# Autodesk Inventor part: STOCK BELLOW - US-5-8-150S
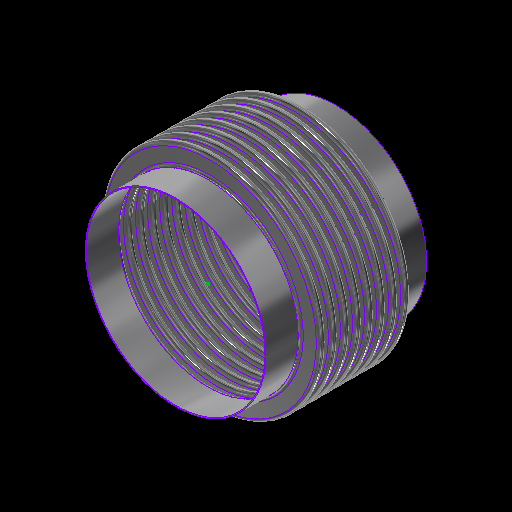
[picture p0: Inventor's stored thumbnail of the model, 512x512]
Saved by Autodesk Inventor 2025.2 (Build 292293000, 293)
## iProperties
Category: 22 GA (0.030 THICK)
RuleStatus: InUse
Created: 2024-01
Part Number: STOCK BELLOW - US-5-8-150S
Project: =STOCK BELLOWS: <Stock Number><SFILL>
Material: ASTM A240-304
Description: =STOCK BELLOWS: <Stock Number>, <SID_> I.D., <SOD_> O.D., <SPLY_> PLY, <Category>, <SNET_CONS> CONS.<PITCH_><STANGENT_> TANGENT<SFILL>
Document SubType Name: Sheet Metal
Designer: GS
Stock Number: U.S-5-8-150S
Surface Area: 3291.39 cm^2
Volume: 124.624 cm^3
Sheet Metal Rule: Default
Appearance: STAINLESS STEEL
Mass: 1004.13 g
Density: 8.05729 g/cm^3
THK: 0.036
ID: 3.500
OD: 4.250
CONS_: 2
PITCH: 0.500
TANGENT: 0.500
BELLOWS_UPSET: 0.000
d79: 1.000
d82: 1.000
d83: 26.000
d84: 24.000
d174: 8
d214: 8
STHK_: 0.030
SID_: 5.563
SOD_: 6.813
SPITCH_: 0.375
STANGENT__: 1.000
SBELLOWS_UPSET_: 0.000
SDIFF_TAN: 1.000
d252: 2
d275: 2
d287: 0.050
d289: 0.500
d290: 0.000
SOD_NECK: 5 5/8
PLY: 1
PSET: 4.178
PBAR: 1.035
COUNTER: 1.500
NET_TUBE: 3.071
CONS: 2
S_CONS: 0
NET_CONS: 2
ID_M: 88.90 mm
OD_M: 107.95 mm
THK_M: 0.91 mm
ID_U: 3.500 in
OD_U: 4.250 in
THK_U: 0.036 in
TANGENT2: 0.500
TAN_TO_TAN: 1.000 in
d80: 2.571
d81: 10
SID: 2.375
SCONS_: 8
SPITCH: 0.250
STANGENT_: 1.000
SBELLOWS_UPSET: 0.000
SNET_CONS: 8
SS_CONS: 0
SCONS: 8
d190: 8
d191: 1
d192: 1
d193: 8
d194: 0
SIZE: 5.00
PRESSURE: 150
d230: 8
STANGENT: 4.000
SPLY_: 1
d233: 8
d234: 0
d263: 2
d265: 1
d268: 2
d269: 0
d286: 2
d288: 1
d291: 2
d292: 0
SREROLL: 0.750
BLETP: 0.000 ul
PRES_Copy: 85
MATTABLE: 20 GA (0.036 THICK)
PART_NUMBER: U.S-5-8-150S
PITCH_: =, <SPITCH_> PITCH,
CFILL: .
SFILL: .
MESH: ,
COMP: 0.69
EXT: 0.35
LAT: 0.11
ANG: 573
ASR: 1531
LSR: 8791
ANSR: 115
PRES: 150
COMPM: 6.9
EXTM: 3.45
LATM: 1.10
ASRM: 268.124
PRESM: 10.342
LSRM: 1539.568
ANSRM: 20.14
TEMPMIN: 20
TEMPMAX: 800
TEMPMINM: -7
TEMPMAXM: 427
WEIGHTM: 1.004
WEIGHT: 2.214
Author: GS
Keywords: 20 GA (0.036 THICK)
Comments: =STOCK BELLOW - <STOCK NUMBER>
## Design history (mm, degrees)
sketch "Sketch2"
  geometry: L1 (0, -177.245)-(0, 562.856) reference; L2 (45.364, 0)-(44.45, 0); L3 (48.082, -2.718)-(50.343, -2.718); L4 (48.082, -3.632)-(50.343, -3.632); L5 (50.343, -9.982)-(48.082, -9.982); L6 (50.343, -9.068)-(48.082, -9.068); L7 (45.364, -12.7)-(44.45, -12.7); L8 (48.082, 0)-(48.082, -12.7); L9 (50.343, -6.35)-(53.975, -6.35); L10 (44.45, 0)-(44.45, -12.7); L11 (20.376, 102.841)-(20.376, 101.926); L12 (58.262, 457.127)-(58.262, 349.177); L13 (58.262, 444.427)-(58.262, 336.477); L14 (93.133, -58.817)-(93.133, -71.517); L15 (118.746, -66.401)-(118.746, -66.401); L16 (50.343, -9.068)-(50.343, -9.982); L17 (48.082, -9.068)-(48.082, -9.982); L18 (48.082, -9.525)-(50.343, -9.525); L19 (53.975, 0)-(53.975, -12.7); L20 (-50.343, -9.068)-(-50.343, -9.982); L21 (-50.343, -2.718)-(-48.082, -2.718); L22 (-50.343, -3.632)-(-48.082, -3.632); L23 (-48.082, -9.068)-(-50.343, -9.068); L24 (-50.343, -9.525)-(-48.082, -9.525); L25 (-48.082, -9.982)-(-50.343, -9.982); L26 (-48.082, -9.068)-(-48.082, -9.982); L27 (-44.45, 0.653)-(-44.45, -12.047); L28 (-48.082, -6.35)-(-44.45, -6.35); L29 (-50.343, 0.653)-(-50.343, -12.7); L30 (-53.061, 0)-(-53.975, 0); L31 (-53.975, 0)-(-53.975, -12.7); L32 (-53.061, -12.7)-(-53.975, -12.7); A1 r 2.718 centre (48.082, 0) between (45.364, 0) and (48.082, -2.718); A2 r 3.632 centre (48.082, 0) between (44.45, 0) and (48.082, -3.632); A3 r 3.632 centre (50.343, -6.35) between (50.343, -9.982) and (50.343, -2.718); A4 r 2.718 centre (50.343, -6.35) between (50.343, -9.068) and (50.343, -3.632); A5 r 2.718 centre (48.082, -12.7) between (48.082, -9.982) and (45.364, -12.7); A6 r 3.632 centre (48.082, -12.7) between (48.082, -9.068) and (44.45, -12.7); A7 r 3.175 centre (50.343, -6.35) between (50.343, -9.525) and (53.518, -6.35); A8 r 3.175 centre (48.082, -12.7) between (48.082, -9.525) and (44.907, -12.7); A9 r 2.718 centre (-50.343, -12.7) between (-50.343, -9.982) and (-53.061, -12.7); A10 r 2.718 centre (-48.082, -6.35) between (-48.082, -9.068) and (-48.082, -3.632); A11 r 3.175 centre (-48.082, -6.35) between (-48.082, -9.525) and (-44.907, -6.35); A12 r 3.632 centre (-48.082, -6.35) between (-48.082, -9.982) and (-48.082, -2.718); A13 r 3.175 centre (-50.343, -12.7) between (-50.343, -9.525) and (-53.518, -12.7); A14 r 3.632 centre (-50.343, -12.7) between (-50.343, -9.068) and (-53.975, -12.7); A15 r 2.718 centre (-50.343, 0) between (-53.061, 0) and (-50.343, -2.718); A16 r 3.632 centre (-50.343, 0) between (-53.975, 0) and (-50.343, -3.632); 10 further points
  constraints: 62 end point, 38 point on circle, 20 tangent, 16 centre point, 12 parallel, 9 midpoint, 7 vertical, 6 coincident, 6 concentric, 6 point on line, 4 equal radius, 4 perpendicular, 3 horizontal, 1 collinear, 1 horizontal alignment, 10 other
  dimensions: "THK" = 0.9144 distance of L11.start L11.end; "ID" = 88.9 distance of L11.end point (20.376, 13.026); "OD" = 107.95 distance of L12.start L12.end; "PITCH" = 12.7 distance of L12.start L13.start; "TANGENT" = 12.7 distance of L14.start L14.end; "BELLOWS_UPSET" = 0 distance of L15.start L15.end; "d43" = 88.9 diameter of L10 L1 (= ID); "d44" = 107.95 diameter of L9.end L1 (= OD); "d45" = 0.9144 distance between parallel lines of L5 L6 (computed from THK, PLY); "d46" = 3.6322 radius of A3 (computed from PITCH, THK, PLY); "UPSET_PITCH" = 12.7 distance of L2.end L7.end (derived); "SIDEWALL_ANGLE" = 360 deg dimension on L3 L9 (derived); "CON_GAP" = 5.4356 distance of point (48.082, -9.068) point (48.082, -3.632) (derived); "TAN1" = 4.98728 dimension on A8 (derived); "TAN2" = 4.98728 dimension on A7 (derived); "LEG1" = 2.2606 distance of L18.start L18.end (derived); "d278" = 0.9144 distance between parallel lines of L25 L23 (derived); "d279" = 3.6322 radius of A12 (derived); "d280" = 12.7 distance of L30.end L31.end (derived); "d281" = 360 deg dimension on L21 L28 (derived); "d282" = 5.4356 distance of point (-50.343, -9.068) point (-50.343, -3.632) (derived); "d283" = 4.98728 dimension on A13 (derived); "d284" = 4.98728 dimension on A11 (derived); "d285" = 2.2606 distance of L24.start L24.end (derived); "d293" = 88.9 diameter of L27 L1 (derived); "d294" = 107.95 diameter of L31 L1 (derived)
  node "Sketch Rectangular Pattern1" dims "d31" = 25.4, "ID" = 88.9
  node "Sketch Rectangular Pattern2" dims "d39" = 25.4, "PITCH" = 12.7
revolve "CONS" stored, may be unused: angle "d48" = 90 deg
node "BELLOW MIDPLANE"
pattern_linear "Rectangular Pattern2" dims "d52" = 12.7 (= UPSET_PITCH)
sketch "Sketch5"
  geometry: C1 r 45.364 at (0, 0) reference; C2 r 44.45 at (0, 0) reference
extrude "TANGENT" new body sketch "Sketch5" distance "d53" = 12.7 (= TANGENT); taper "d54" = 0 deg
revolve "SAMETAN" stored, may be unused: angle "d65" = 90 deg
revolve "DIFFTAN" stored, may be unused: angle "d70" = 90 deg
sketch "Sketch9"
  geometry: L1 (53.319, 0)-(-53.319, 0) reference; L2 (0, -17.78)-(0, 17.78) reference; L3 (38.085, 0)-(-38.085, 0); L4 (38.085, -11.906)-(38.085, 11.906); L5 (25.385, -11.906)-(25.385, 11.906); L6 (13.15, 11.906)-(13.15, -11.906); L7 (-25.385, -11.906)-(-25.385, 11.906); L8 (-38.085, -11.906)-(-38.085, 11.906); L9 (37.291, -11.906)-(37.291, 11.906); L10 (38.085, -11.906)-(37.291, -11.906); L11 (38.085, 11.906)-(37.291, 11.906); L12 (13.546, 11.906)-(12.753, 11.906); L13 (12.753, 11.906)-(12.753, -11.906); L14 (12.753, -11.906)-(13.546, -11.906); L15 (13.546, -11.906)-(13.546, 11.906); L16 (-13.546, 11.906)-(-13.546, -11.906); L17 (-13.15, 11.906)-(-13.15, -11.906); L18 (-13.546, -11.906)-(-12.753, -11.906); L19 (-12.753, -11.906)-(-12.753, 11.906); L20 (-12.753, 11.906)-(-13.546, 11.906); L21 (-38.085, -11.906)-(-37.291, -11.906); L22 (-37.291, -11.906)-(-37.291, 11.906); L23 (-37.291, 11.906)-(-38.085, 11.906); L24 (-38.085, 11.906)-(-38.085, -11.906); L25 (38.085, -0.397)-(-38.085, -0.397); L26 (-38.085, -0.397)-(-38.085, 0.397); L27 (-38.085, 0.397)-(38.085, 0.397); L28 (38.085, 0.397)-(38.085, -0.397); L29 (-38.085, 11.906)-(38.085, 11.906); L30 (38.085, 11.906)-(38.085, 12.7); L31 (38.085, 12.7)-(-38.085, 12.7); L32 (-38.085, 12.7)-(-38.085, 11.906); L33 (38.085, -11.906)-(-38.085, -11.906); L34 (-38.085, -11.906)-(-38.085, -12.7); L35 (-38.085, -12.7)-(38.085, -12.7); L36 (38.085, -12.7)-(38.085, -11.906); 30 further points
  constraints: 68 end point, 13 midpoint, 13 parallel, 8 horizontal, 7 perpendicular, 6 equal length, 3 point on line, 2 vertical, 14 other
  dimensions: "d115" = 23.8125 distance of L4.start L4.end (derived); "d116" = 12.7 distance between parallel lines of L4 L5 (derived); "d117" = 12.23516 distance between parallel lines of L5 L6 (derived); "d125" = 38.53427 distance between parallel lines of L7 L6 (derived); "d127" = 12.7 distance between parallel lines of L8 L7 (derived); "d128" = 24.93516 distance between parallel lines of L6 L4 (derived); "d130" = 76.16943 distance between parallel lines of L8 L4 (derived); "RULER_THK" = 0.79375 distance between parallel lines of L4 L9; "d135" = 0.79375 distance of L13.end L14.end (derived); "d138" = 26.29911 distance of L13.end L16.end (derived); "d143" = 0.79375 distance of L22.end L8.end (derived); "d144" = 0.79375 distance between parallel lines of L27 L25 (derived)
extrude "RULER" join sketch "Sketch9" distance "d149" = 0.79375 (derived); taper "d150" = 0 deg
extrude "BARS" join sketch "Sketch9" distance "d151" = 0.79375 (derived); taper "d152" = 0 deg
pattern_linear "Rectangular Pattern4" dims "d155" = 26.29911 (derived)
sketch "Sketch13"
  geometry: L1 (93.149, -52.467)-(93.149, -77.867); L2 (71.412, 0)-(70.65, 0); L3 (71.412, -9.525)-(70.65, -9.525); L4 (83.763, -7.525)-(73.412, -7.525); L5 (83.763, -6.763)-(73.412, -6.763); L6 (83.763, -4.763)-(86.525, -4.763); L7 (73.412, -2)-(83.763, -2); L8 (73.412, 0)-(73.412, -9.525); L9 (70.65, 0)-(70.65, -9.525); L10 (58.254, -323.381)-(58.254, -496.431); L11 (58.254, -332.906)-(58.254, -505.956); L12 (58.254, -351.956)-(58.254, -525.006); L13 (58.254, -361.481)-(58.254, -534.531); L14 (58.254, -371.006)-(58.254, -544.056); L15 (58.254, -380.531)-(58.254, -553.581); L16 (58.254, -390.056)-(58.254, -563.106); L17 (58.254, -342.431)-(58.254, -515.481); L18 (20.376, 102.688)-(20.376, 101.926); L19 (73.412, -2.762)-(83.763, -2.762); L20 (0, -696.265)-(0, 235.847) reference; L21 (-23.752, 0)-(142.514, 0) reference; A1 r 2 centre (73.412, 0) between (71.412, 0) and (73.412, -2); A2 r 2 centre (73.412, -9.525) between (73.412, -7.525) and (71.412, -9.525); A3 r 2.762 centre (73.412, -9.525) between (73.412, -6.763) and (70.65, -9.525); A4 r 2 centre (83.763, -4.763) between (83.763, -6.763) and (83.763, -2.762); A5 r 2.762 centre (83.763, -4.763) between (83.763, -7.525) and (83.763, -2); A6 r 2.762 centre (73.412, 0) between (70.65, 0) and (73.412, -2.762); 6 further points; 1 other entity
  constraints: 38 end point, 15 point on circle, 9 tangent, 6 centre point, 6 parallel, 5 vertical alignment, 4 point on line, 4 vertical, 3 coincident, 3 concentric, 2 collinear, 2 equal radius, 1 horizontal, 1 perpendicular, 23 other
  dimensions: "SBELLOWS_UPSET_" = 0 distance of point (118.762, -66.401) point (118.762, -66.401); "STOTAL_THK_BELLOW__" = 0.762 distance between parallel lines of L4 L5 (derived); "d224" = 2.76225 radius of A5 (derived); "d225" = 9.525 distance of L2.end L3.end (derived); "SSIDEWALL_ANGLE_" = 360 deg dimension on L7 L6 (derived); "SSCON_GAP_" = 4.0005 distance of point (73.412, -6.763) point (73.412, -2.762) (derived); "d235" = 141.3002 diameter of L9 L20 (derived); "d236" = 173.0502 diameter of L6.end L20 (derived)
  node "Sketch Rectangular Pattern4" dims "d228" = 25.4
  node "Sketch Rectangular Pattern5" dims "d229" = 25.4
revolve "SBELLOW" stored, may be unused: angle "d197" = 90 deg
pattern_linear "Rectangular Pattern5" dims "d204" = 9.525 (derived)
revolve "STANGENT" stored, may be unused: angle "d240" = 90 deg
revolve "SSAMETAN" stored, may be unused: angle "d241" = 90 deg
revolve "SDIFFTAN" stored, may be unused: angle "d246" = 90 deg
revolve "INVCON" stored, may be unused: angle "d295" = 90 deg
pattern_linear "Rectangular Pattern6" dims "d298" = 12.7 (derived)
revolve "INVTANGENT" stored, may be unused: angle "d302" = 90 deg
revolve "INVSAMETAN" stored, may be unused: angle "d307" = 90 deg
revolve "INVDIFFTAN" stored, may be unused: angle "d312" = 90 deg
sketch "ID BELLOW MOUNT CALC"
  geometry: L1 (44.45, 0)-(38.1, 0); L2 (38.1, 0)-(38.1, 12.7); L3 (38.1, 12.7)-(44.45, 12.7); L4 (44.45, 12.7)-(44.45, 0); L5 (36.513, 12.7)-(35.598, 12.7); L6 (35.598, 12.7)-(35.598, 0); L7 (35.598, 0)-(36.513, 0); L8 (36.513, 0)-(36.513, 12.7); L9 (0, -2.54)-(0, 15.24) reference; L10 (-8.89, 0)-(53.34, 0) reference; 1 further point
  constraints: 16 end point, 5 parallel, 2 collinear, 2 horizontal, 2 perpendicular
  dimensions: "d314" = 12.7 distance of L5.end L6.end (derived); "d315" = 0.9144 distance of L5.start L5.end (derived); "IG" = 1.5875 distance between parallel lines of L2 L8; "PIPE_OD" = 88.9 diameter of L4 L9; "PIPE_WALL" = 6.35 distance of L2.end L3.end; "ID_MT_BELLOW" = 71.1962 diameter of L6 L9 (derived)
revolve "CFILL" stored, may be unused: angle "d320" = 90 deg
pattern_linear "Rectangular Pattern7" dims "d323" = 12.7 (derived)
revolve "SFILL" stored, may be unused: angle "d324" = 90 deg
pattern_linear "Rectangular Pattern8" dims "d327" = 9.525 (derived)
node "STOCK BELLOW MIDPLANE"
node "BELLOW"
sketch "Sketch6"
  geometry: L1 (-12.7, 45.364)-(0, 45.364); L2 (0, 45.364)-(0, 44.45); L3 (0, 44.45)-(-12.7, 44.45); L4 (-12.7, 44.45)-(-12.7, 45.364); L5 (10.16, 0)-(-60.96, 0) reference; L6 (-38.1, -89.422)-(-38.1, 153.44) reference; 1 further point
  constraints: 8 end point, 2 parallel, 1 horizontal, 1 perpendicular
  dimensions: "d61" = 12.7 distance of L2.end L3.end (derived); "d62" = 0.9144 distance of L1.end L2.end (derived); "d63" = 88.9 diameter of L3 L5 (derived); "d64" = 25.4 distance between parallel lines of L4 L6 (derived)
sketch "Sketch12"
  geometry: 1 further point
sketch "Sketch14"
  geometry: L1 (-25.4, 71.412)-(0, 71.412); L2 (0, 71.412)-(0, 70.65); L3 (0, 70.65)-(-25.4, 70.65); L4 (-25.4, 70.65)-(-25.4, 71.412); L5 (5.08, 0)-(-30.48, 0) reference; L6 (0, -14.282)-(0, 85.695) reference; 1 further point
  constraints: 8 end point, 2 parallel, 1 collinear, 1 horizontal, 1 perpendicular
  dimensions: "d237" = 0.762 distance of L3.end L1.start (derived); "d238" = 141.3002 diameter of L3 L5 (derived); "d239" = 25.4 distance of L1.start L1.end (derived); "SOD_NECK" = 142.8242 diameter of L1 L5 (derived)
sketch "Sketch15"
  geometry: L1 (-14.282, 0)-(85.695, 0) reference; L2 (70.65, -76.2)-(71.412, -76.2); L3 (71.412, -76.2)-(71.412, -101.6); L4 (71.412, -101.6)-(70.65, -101.6); L5 (70.65, -101.6)-(70.65, -76.2); L6 (0, -124.46)-(0, 35.56) reference; 1 further point
  constraints: 8 end point, 2 parallel, 1 horizontal, 1 perpendicular
  dimensions: "d205" = 25.4 distance of L4.end L2.start (derived); "d206" = 0.762 distance of L3.end L4.end (derived); "d207" = 141.3002 diameter of L5 L6 (derived); "d208" = 76.2 distance between parallel lines of L1 L2 (derived)
node "TANGENT_"
node "SAME_TAN"
sketch "Sketch8"
  geometry: L1 (45.364, -25.4)-(44.45, -25.4); L2 (44.45, -25.4)-(44.45, -38.1); L3 (44.45, -38.1)-(45.364, -38.1); L4 (45.364, -38.1)-(45.364, -25.4); L5 (0, -48.26)-(0, 22.86) reference; L6 (-89.422, 0)-(153.44, 0) reference; 1 further point
  constraints: 8 end point, 2 parallel, 1 horizontal, 1 perpendicular
  dimensions: "d66" = 88.9 diameter of L2 L5 (derived); "TOTAL_THK_BELLOW" = 0.9144 distance of L2.end L3.end (derived); "d68" = 25.4 distance between parallel lines of L1 L6 (derived); "d69" = 12.7 distance of L1.end L2.end (derived)
node "DIFF_TAN"
node "Sketch Rectangular Pattern3" dims "d138" = 26.29911 (derived), "d141" = 25.4
node "SBELLOW_"
node "STANGENT_"
node "SSAME_TAN"
sketch "Sketch16"
  geometry: L1 (71.412, -76.2)-(70.65, -76.2); L2 (70.65, -76.2)-(70.65, -101.6); L3 (70.65, -101.6)-(71.412, -101.6); L4 (71.412, -101.6)-(71.412, -76.2); L5 (0, -124.46)-(0, 35.56) reference; L6 (-14.282, 0)-(85.695, 0) reference; 1 further point
  constraints: 8 end point, 2 parallel, 1 horizontal, 1 perpendicular
  dimensions: "SDIFF_TAN" = 25.4 distance of L3.end L1.start; "d243" = 0.762 distance of L2.end L3.end (derived); "d244" = 76.2 distance between parallel lines of L1 L6 (derived); "d245" = 141.3002 diameter of L2 L5 (derived)
node "SDIFF_TAN"
body "Solid15"
sketch "Sketch17"
  geometry: L1 (53.975, 12.7)-(53.061, 12.7); L2 (53.061, 12.7)-(53.061, 0); L3 (53.061, 0)-(53.975, 0); L4 (53.975, 0)-(53.975, 12.7); L5 (0, -2.54)-(0, 15.24) reference; L6 (-10.795, 0)-(64.77, 0) reference; 2 further points
  constraints: 8 end point, 2 parallel, 1 horizontal, 1 midpoint, 1 perpendicular, 1 point on line
  dimensions: "INVTANGENT" = 12.7 distance of L3.end L1.start (derived); "d300" = 0.9144 distance of L1.start L1.end (derived); "d301" = 107.95 diameter of L4 L5 (derived)
body "Solid16"
sketch "Sketch18"
  geometry: L1 (53.975, -25.4)-(53.061, -25.4); L2 (53.061, -25.4)-(53.061, -38.1); L3 (53.061, -38.1)-(53.975, -38.1); L4 (53.975, -38.1)-(53.975, -25.4); L5 (-10.795, 0)-(64.77, 0) reference; L6 (0, -48.26)-(0, 22.86) reference; 1 further point
  constraints: 8 end point, 2 parallel, 1 horizontal, 1 perpendicular
  dimensions: "d303" = 25.4 distance between parallel lines of L1 L5 (derived); "d304" = 12.7 distance of L3.end L1.start (derived); "d305" = 0.9144 distance of L2.end L3.end (derived); "d306" = 107.95 diameter of L4 L6 (derived)
body "Solid17"
sketch "Sketch19"
  geometry: L1 (53.975, -25.4)-(53.061, -25.4); L2 (53.061, -25.4)-(53.061, -38.1); L3 (53.061, -38.1)-(53.975, -38.1); L4 (53.975, -38.1)-(53.975, -25.4); L5 (0, -48.26)-(0, 22.86) reference; L6 (-10.795, 0)-(64.77, 0) reference; 1 further point
  constraints: 8 end point, 2 parallel, 1 horizontal, 1 perpendicular
  dimensions: "d308" = 12.7 distance of L1.end L2.end (derived); "d309" = 107.95 diameter of L4 L5 (derived); "d310" = 0.9144 distance of L2.end L3.end (derived); "d311" = 25.4 distance between parallel lines of L1 L6 (derived)
body "Solid18"
body "Solid19"
body "Solid20"
other parameters: "BMPL" = -38.1, "PSET" = 106.1212 (computed from OD, THK, PLY) [user parameter], "PBAR" = 26.29911 (= 0.570796 x PITCH + OD - ID) [user parameter; used in 1 equation term], "COUNTER" = 15 [user parameter], "NET_TUBE" = 77.99823 (computed from CONS_, PBAR, TANGENT) [user parameter], "S_CONS" = 0 [user parameter; used in 1 equation term], "ID_M" = 88.9 (= ID) [user parameter], "OD_M" = 107.95 (= OD) [user parameter], "THK_M" = 0.9144 (= THK) [user parameter], "ID_U" = 88.9 (= ID) [user parameter], "OD_U" = 107.95 (= OD) [user parameter], "THK_U" = 0.9144 (= THK) [user parameter], "D_UNITS" = 0 [user parameter], "TANGENT2" = 12.7 [user parameter], "TAN_TO_TAN" = 25.4 [user parameter], "OD_NECK" = 90.7288 [user parameter], "d79" = 25.4, "d80" = 65.29823 [user parameter], "d82" = 25.4, "d83" = 660.4, "d84" = 609.6, "sa_0" = 4, "FRAME_THK" = 0.79375 [user parameter], "CON_FLAT" = 12.23516 [user parameter], "SID" = 60.325 [user parameter], "SPITCH" = 6.35 [user parameter], "STANGENT_" = 25.4 [user parameter], "SBELLOWS_UPSET" = 0 [user parameter], "SS_CONS" = 0 [user parameter], "STAN_TO_TAN_" = 76.2 [user parameter], "d100" = 0.762 [user parameter], "d191" = 25.4 [user parameter], "d194" = 0 [user parameter], "STANGENT" = 101.6 [user parameter], "d234" = 0 [user parameter], "SUPSET_PITCH_" = 9.525 [user parameter], "d269" = 0 [user parameter], "d287" = 1.27, "d289" = 12.7, "d290" = 0, "d292" = 0 [user parameter], "Thickness" = 3.048 (derived), "KFactor" = 4.4, "BendRadius" = 3.048 (derived), "BendReliefWidth" = 3.048 (derived), "BendReliefDepth" = 1.524 (derived), "CornerReliefSize" = 12.192 (derived), "SeamGap" = 0.00508, "MinimumRemnant" = 6.096 (derived), "TransitionRadius" = 3.048 (derived), "JacobiRadiusSize" = 3.048 (derived), "GapSize" = 3.048 (derived), "SREROLL" = 19.05 [user parameter], "CUR_STK_PITCH" = 9.525 [user parameter], "d328" = -38.1 (derived), "ASR" = 15310 [user parameter], "LSR" = 87910 [user parameter], "BLETP" = 0 [user parameter], "ASRM" = 2681.2403 [user parameter], "PRESM" = 103.41975 [user parameter], "LSRM" = 15395.6783 [user parameter], "ANSRM" = 201.3995 [user parameter], "TEMPMIN" = 2664.83333 [user parameter], "TEMPMAX" = 6998.16667 [user parameter], "TEMPMINM" = 2664.83333 [user parameter], "TEMPMAXM" = 6998.16667 [user parameter], "WEIGHT" = 10.04134 [user parameter], "WEIGHTM" = 0.01004 [user parameter]
